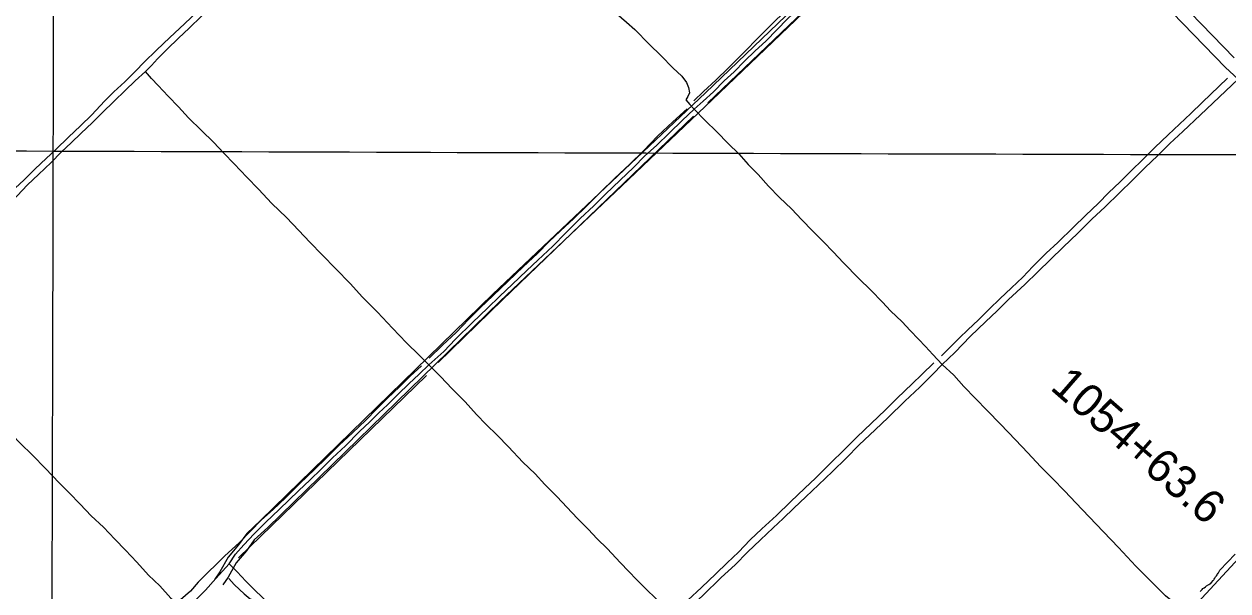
# Model space of a CAD drawing. Extents: x 3161514 to 3199414, y 831166 to 856601.
# Drawn here: x 3191795 to 3195450, y 841285 to 843007 of the extents above; entities that cross this region are included whole.
import ezdxf

# ---------------------------------------------------------------- set-up
doc = ezdxf.new("R2010")
doc.units = 0
for name, color, linetype in [('V-GRID-MAJR', 7, 'Continuous'), ('V-ROAD-CNTR', 7, 'Continuous'), ('V-SITE-VEGE', 7, 'Continuous'), ('V-SURV-IDEN', 7, 'Continuous'), ('V-TOPO-SHOR', 7, 'Continuous')]:
    doc.layers.add(name, color=color, linetype=linetype)

msp = doc.modelspace()

# ---------------------------------------------------------------- linework, layer by layer
at = {"layer": 'V-GRID-MAJR'}
for points in [[(3191868.813, 836560.569), (3191883.798, 842621.023), (3191898.788, 848683.42), (3191913.778, 854745.858), (3191913.7830000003, 854747.76)], [(3165722.25, 842695.223), (3170954.554, 842678.861), (3176186.862, 842663.26), (3181419.1720000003, 842648.42), (3186651.484, 842634.341), (3191883.798, 842621.023), (3197116.113, 842608.466), (3197116.114, 842608.466)]]:
    msp.add_spline(points, degree=3, dxfattribs=at)
at = {"layer": 'V-ROAD-CNTR'}
for points in [[(3195091.441780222, 843982.0380084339), (3194693.490576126, 843594.0597843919), (3193863.4942361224, 842798.0953763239), (3193579.1478048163, 842528.3749157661)], [(3195117.135728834, 843965.1910421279), (3194714.344534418, 843572.493827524), (3193884.20019471, 842776.3854197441), (3193609.337744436, 842515.6619411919)], [(3193579.1478048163, 842528.3749157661), (3193218.165526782, 842185.9616005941), (3192514.1949347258, 841500.0619723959), (3192470.860021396, 841459.9950525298), (3192446.21307069, 841425.42012168), (3192414.4181342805, 841387.4101977), (3192389.409184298, 841343.0502864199), (3192373.6412158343, 841321.1523302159)], [(3193609.337744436, 842515.6619411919), (3193238.957485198, 842164.3336438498), (3192534.8488934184, 841478.3020159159), (3192493.495976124, 841440.0650923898), (3192469.9690231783, 841407.062158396), (3192439.1980847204, 841370.276231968), (3192414.7251336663, 841326.87031878), (3192397.987167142, 841303.6223652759)]]:
    msp.add_lwpolyline(points, dxfattribs=at)
at = {"layer": 'V-SITE-VEGE'}
for p, q in [((3195365.9050000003, 842730.7270000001), (3195480.833, 842839.7050000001)), ((3195425.404, 841348.042), (3195471.4220000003, 841396.659)), ((3195419.633, 841338.8420000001), (3195420.943, 841340.473)), ((3195420.943, 841340.473), (3195422.254, 841342.756)), ((3195422.254, 841342.756), (3195424.5500000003, 841346.344)), ((3195424.5500000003, 841346.344), (3195425.404, 841348.042)), ((3195384.921, 841300.707), (3195392.1180000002, 841304.936)), ((3195392.1180000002, 841304.936), (3195395.063, 841307.2170000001)), ((3195395.063, 841307.2170000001), (3195397.35, 841308.1900000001)), ((3195397.35, 841308.1900000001), (3195400.2970000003, 841311.121)), ((3195400.2970000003, 841311.121), (3195404.557, 841316.667)), ((3195404.557, 841316.667), (3195406.849, 841318.946)), ((3195406.849, 841318.946), (3195407.832, 841321.234)), ((3195407.832, 841321.234), (3195409.8000000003, 841324.492)), ((3195409.8000000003, 841324.492), (3195412.4220000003, 841327.7519999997)), ((3195412.4220000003, 841327.7519999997), (3195415.043, 841331.666)), ((3195415.043, 841331.666), (3195417.3370000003, 841334.601)), ((3195417.3370000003, 841334.601), (3195418.322, 841336.561)), ((3195418.322, 841336.561), (3195419.633, 841338.8420000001)), ((3195364.957, 841283.4400000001), (3195366.921, 841285.3960000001)), ((3195366.921, 841285.3960000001), (3195371.179, 841289.9589999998)), ((3195371.179, 841289.9589999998), (3195373.796, 841292.238)), ((3195373.796, 841292.238), (3195377.069, 841294.518)), ((3195377.069, 841294.518), (3195381.323, 841297.774)), ((3195381.323, 841297.774), (3195384.921, 841300.707))]:
    msp.add_line(p, q, dxfattribs=at)
for points in [[(3195480.833, 842839.7050000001), (3195442.685, 842874.5), (3195248.278, 843075.393), (3194937.003, 843402.0750000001), (3194730.659, 843612.049)], [(3194435.786, 843338.653), (3194393.843, 843296.902), (3194364.2290000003, 843268.837), (3194327.166, 843232.8250000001), (3194295.424, 843202.109), (3194266.254, 843175.544), (3194239.208, 843148.005), (3194214.821, 843122.403), (3194182.718, 843090.095), (3194146.008, 843053.465), (3194111.608, 843021.34), (3194081.721, 842990.2660000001)], [(3193509.893, 843119.605), (3193558.7970000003, 843071.721), (3193593.048, 843038.465), (3193623.512, 843012.208), (3193649.1180000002, 842990.208), (3193692.4560000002, 842945.343), (3193728.646, 842909.605), (3193764.132, 842873.4400000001)], [(3192370.838, 843066.801), (3192333.362, 843030.112), (3192296.328, 842994.1240000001), (3192263.882, 842963.756), (3192228.965, 842930.669), (3192199.6890000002, 842900.997), (3192181.429, 842880.804), (3192163.2120000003, 842862.5480000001)], [(3194081.721, 842990.2660000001), (3194046.34, 842954.5160000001), (3194014.776, 842925.3030000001), (3193982.059, 842893.4400000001), (3193950.756, 842861.307), (3193919.9930000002, 842833.952), (3193888.0670000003, 842800.318), (3193856.947, 842772.2540000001), (3193829.291, 842748.1630000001)], [(3192163.2120000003, 842862.5480000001), (3192132.447, 842833.952), (3192101.944, 842804.385), (3192068.429, 842772.082), (3192032.253, 842737.041), (3192002.282, 842708.1780000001)], [(3192369.569, 842648.4180000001), (3192333.286, 842683.18), (3192294.534, 842721.488), (3192263.294, 842754.914), (3192232.136, 842787.188), (3192202.485, 842819.8150000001), (3192181.921, 842841.36), (3192163.2120000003, 842862.5480000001)], [(3193764.132, 842873.4400000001), (3193791.679, 842848.605), (3193805.526, 842829.5530000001), (3193812.5670000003, 842814.408), (3193815.36, 842797.68), (3193810.0270000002, 842786.279), (3193804.342, 842776.561), (3193815.633, 842761.848), (3193829.291, 842748.1630000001)], [(3193829.291, 842748.1630000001), (3193792.828, 842714.238), (3193754.08, 842676.549), (3193714.623, 842637.889), (3193679.25, 842606.03), (3193644.668, 842571.341), (3193605.0330000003, 842532.769), (3193560.432, 842489.8740000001), (3193524.696, 842454.39), (3193482.7630000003, 842416.088), (3193439.665, 842372.394), (3193399.7600000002, 842331.789)], [(3193829.291, 842748.1630000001), (3193862.7660000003, 842713.3470000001), (3193898.429, 842679.027), (3193932.588, 842644.1780000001), (3193964.631, 842612.698), (3193993.487, 842580.252), (3194023.144, 842549.837), (3194055.267, 842514.2880000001), (3194088.279, 842480.416), (3194124.649, 842445.387)], [(3194993.946, 842371.409), (3195036.954, 842414.485), (3195076.7630000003, 842451.818), (3195120.387, 842494.007), (3195160.11, 842532.579), (3195198.418, 842571.0650000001), (3195235.745, 842606.014), (3195273.078, 842643.617), (3195312.707, 842679.9770000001), (3195365.9050000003, 842730.7270000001)], [(3192002.282, 842708.1780000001), (3191967.79, 842674.55), (3191939.063, 842646.746), (3191908.031, 842617.976), (3191876.906, 842586.552), (3191838.954, 842549.3030000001), (3191805.265, 842518.06), (3191774.401, 842485.221), (3191736.454, 842449.389), (3191701.9620000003, 842416.289), (3191676.251, 842392.551)], [(3192822.883, 842177.773), (3192784.758, 842218.647), (3192741.772, 842262.98), (3192699.936, 842305.984), (3192662.779, 842344.732), (3192628.975, 842380.197), (3192591.64, 842419.033), (3192547.413, 842461.601), (3192507.08, 842504.867), (3192471.156, 842541.577), (3192433.1180000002, 842582.626), (3192401.784, 842614.724), (3192369.569, 842648.4180000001)], [(3194124.649, 842445.387), (3194155.716, 842412.14), (3194188.903, 842378.268), (3194221.915, 842345.103), (3194251.132, 842315.31), (3194283.0810000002, 842281.3520000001)], [(3194581.771, 841973.202), (3194620.3000000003, 842009.796), (3194668.275, 842059.052), (3194713.761, 842102.388), (3194749.3140000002, 842135.572), (3194783.276, 842169.9990000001), (3194832.747, 842215.626), (3194872.739, 842254.46), (3194910.776, 842291.4450000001), (3194949.436, 842329.044), (3194993.946, 842371.409)], [(3193399.7600000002, 842331.789), (3193354.544, 842289.692), (3193321.119, 842258.095), (3193276.431, 842215.552), (3193239.281, 842179.897), (3193201.862, 842143.973), (3193156.8200000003, 842100.813), (3193105.2120000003, 842049.441), (3193069.387, 842012.63), (3193024.136, 841971.721)], [(3194283.0810000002, 842281.3520000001), (3194329.066, 842234.003), (3194365.171, 842198.974), (3194400.74, 842161.911), (3194425.275, 842135.934), (3194460.323, 842102.589), (3194485.3880000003, 842076.432), (3194510.276, 842049.568), (3194531.634, 842027.136), (3194553.433, 842003.0210000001), (3194581.771, 841973.202)], [(3193024.136, 841971.721), (3192994.471, 842001.587), (3192955.717, 842038.834), (3192913.794, 842083.52), (3192868.253, 842131.576), (3192822.883, 842177.773)], [(3192770.6350000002, 841726.349), (3192813.465, 841769.6020000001), (3192844.85, 841798.373), (3192871.544, 841826.002), (3192898.5840000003, 841850.889), (3192930.418, 841882.932), (3192963.046, 841913.822), (3192994.698, 841943.7440000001), (3193024.136, 841971.721)], [(3193024.136, 841971.721), (3193058.823, 841936.252), (3193094.8370000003, 841899.456), (3193133.583, 841859.022), (3193168.975, 841821.255), (3193197.745, 841790.578), (3193231.379, 841758.385), (3193265.536, 841722.652)], [(3194804.727, 841744.348), (3194759.626, 841791.694), (3194718.758, 841832.838), (3194683.0100000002, 841869.725), (3194648.237, 841906.167), (3194617.349, 841940.211), (3194581.771, 841973.202), (3194553.832, 841943.011)], [(3194553.832, 841943.011), (3194514.374, 841903.73), (3194468.625, 841861.721), (3194418.349, 841811.496), (3194378.362, 841774.429), (3194329.865, 841729.066), (3194290.2260000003, 841688.7270000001), (3194248.994, 841647.769)], [(3191738.867, 841780.365), (3191782.112, 841734.702), (3191821.8370000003, 841696.302), (3191858.554, 841657.911), (3191902.154, 841612.515), (3191932.255, 841582.718), (3191965.7090000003, 841549.111), (3191998.539, 841513.381), (3192035.97, 841478.438), (3192070.041, 841442.885), (3192102.52, 841409.013)], [(3195072.245, 841464.786), (3195028.467, 841510.094), (3194987.955, 841552.654), (3194954.065, 841588.473), (3194917.524, 841626.601), (3194881.068, 841662.7810000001), (3194841.882, 841704.273), (3194804.727, 841744.348)], [(3192417.31, 841367.471), (3192436.696, 841396.672), (3192462.3310000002, 841425.188), (3192493.9930000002, 841458.824), (3192529.196, 841494.398), (3192569.095, 841532.35), (3192599.862, 841561.652), (3192628.59, 841589.542), (3192663.702, 841622.9940000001), (3192696.421, 841654.9450000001), (3192731.444, 841689.192), (3192770.6350000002, 841726.349)], [(3193265.536, 841722.652), (3193309.312, 841676.2810000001), (3193346.125, 841640.986), (3193375.866, 841608.449), (3193412.937, 841571.028), (3193442.237, 841539.2000000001), (3193474.719, 841505.419), (3193507.288, 841472.964), (3193535.18, 841443.262), (3193565.545, 841413.8200000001)], [(3194248.994, 841647.769), (3194206.346, 841607.878), (3194168.219, 841570.805), (3194131.955, 841536.296), (3194099.416, 841505.4940000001), (3194068.915, 841476.724), (3194030.968, 841440.714), (3193991.599, 841402.582), (3193953.469, 841364.539)], [(3195305.915, 841239.711), (3195286.472, 841248.78), (3195260.511, 841270.2490000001), (3195221.759, 841308.735), (3195170.299, 841360.785), (3195116.991, 841417.438), (3195072.245, 841464.786)], [(3193565.545, 841413.8200000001), (3193605.703, 841370.908), (3193629.707, 841345.019), (3193654.863, 841318.9500000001), (3193679.668, 841294.919), (3193716.565, 841257.942), (3193750.457, 841223.005), (3193771.9020000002, 841199.247), (3193807.117, 841162.098), (3193845.949, 841120.87)], [(3192102.52, 841409.013), (3192137.383, 841372.483), (3192173.125, 841333.387), (3192206.757, 841300.84), (3192240.836, 841263.1240000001)], [(3192240.836, 841263.1240000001), (3192260.2630000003, 841246.801), (3192279.674, 841223.755), (3192310.703, 841252.171), (3192345.464, 841287.214), (3192377.218, 841322.708), (3192417.31, 841367.471), (3192441.494, 841343.086), (3192468.504, 841315.421), (3192497.72, 841285.7170000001), (3192534.973, 841249.801), (3192566.316, 841221.064)], [(3193953.469, 841364.539), (3193911.713, 841326.415), (3193856.028, 841271.6), (3193820.65, 841238.595), (3193776.403, 841194.9010000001), (3193742.091, 841162.866), (3193700.326, 841121.201)]]:
    msp.add_lwpolyline(points, dxfattribs=at)
at = {"layer": 'V-TOPO-SHOR'}
for p, q in [((3193871.144517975, 842767.2020910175), (3194729.8649335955, 843590.5113554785)), ((3195371.374, 842768.086), (3195448.098, 842842.779)), ((3193016.8504962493, 841939.4664326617), (3192445.845683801, 841386.1671957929))]:
    msp.add_line(p, q, dxfattribs=at)
for points in [[(3195469.0727140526, 842904.4203017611), (3194769.70247865, 843625.9225066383), (3195207.9154742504, 844059.7091083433), (3195584.158955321, 844413.8206199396)], [(3193844.5861546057, 839659.8735767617), (3194672.3218129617, 840514.1675984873), (3194902.494295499, 840748.7664749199), (3195066.270869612, 840885.9846856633), (3195345.133684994, 841235.6698033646), (3195659.407651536, 841576.5021332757), (3196354.351493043, 842337.8418832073), (3196827.975639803, 842882.2883322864), (3196947.4882749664, 843023.9329369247), (3197022.736971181, 843094.755239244), (3197124.5440307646, 843196.5622988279)], [(3194219.4020000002, 843155.605), (3194173.271, 843110.559), (3194123.881, 843062.621), (3194072.1180000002, 843013.814), (3194023.6950000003, 842964.995), (3193982.049, 842922.487)], [(3192001.009, 842731.083), (3192038.651, 842772.334), (3192067.22, 842800.858), (3192101.0470000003, 842831.525), (3192133.502, 842863.486), (3192159.399, 842891.243), (3192197.199, 842926.894), (3192237.3310000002, 842965.468), (3192266.845, 842992.959), (3192300.418, 843024.9180000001), (3192335.287, 843058.853), (3192366.88, 843090.902)], [(3193982.049, 842922.487), (3193933.8880000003, 842874.109), (3193895.417, 842836.426), (3193858.092, 842801.551), (3193827.896, 842773.333)], [(3195371.374, 842768.086), (3195337.508, 842734.638), (3195302.682, 842702.329), (3195268.734, 842670.544), (3195227.764, 842631.333)], [(3191634.836, 842375.843), (3191669.335, 842412.523), (3191703.944, 842445.598), (3191733.722, 842475.4130000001), (3191768.2430000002, 842508.058), (3191794.824, 842533.402), (3191828.401, 842566.909), (3191862.316, 842598.0920000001), (3191890.972, 842626.1), (3191929.896, 842663.558), (3191966.315, 842698.008), (3192001.009, 842731.083)], [(3193807.9790000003, 842749.677), (3193764.406, 842709.544), (3193719.072, 842667.22), (3193675.134, 842621.8200000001), (3193632.611, 842580.3690000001), (3193588.86, 842538.743), (3193544.136, 842494.75)], [(3193826.8805790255, 842727.3645459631), (3193247.022978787, 842169.6389151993), (3193052.261647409, 841979.3039777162)], [(3195227.764, 842631.333), (3195190.3880000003, 842594.1290000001), (3195156.788, 842561.818), (3195122.046, 842527.145), (3195087.13, 842493.611), (3195056.772, 842463.219), (3195017.381, 842424.88), (3194980.8850000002, 842389.511)], [(3193544.136, 842494.75), (3193502.139, 842453.208), (3193463.844, 842415.875), (3193423.1750000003, 842378.458), (3193387.961, 842345.072), (3193353.184, 842310.1900000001), (3193310.1350000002, 842269.179), (3193263.216, 842225.1020000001)], [(3194980.8850000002, 842389.511), (3194933.773, 842343.6630000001), (3194898.247, 842311.268), (3194856.924, 842270.746), (3194827.001, 842238.25), (3194792.3510000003, 842205.767), (3194756.998, 842172.671), (3194725.852, 842141.755)], [(3193263.216, 842225.1020000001), (3193219.198, 842182.162), (3193179.231, 842144.481), (3193145.068, 842110.123), (3193106.326, 842069.806), (3193065.7430000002, 842031.337), (3193024.4560000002, 841991.9)], [(3194725.852, 842141.755), (3194692.4250000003, 842108.831), (3194660.056, 842078.5310000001), (3194635.052, 842053.551), (3194579.781, 841999.5800000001)], [(3193001.717, 841968.8150000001), (3192966.772, 841937.272), (3192934.548, 841905.02), (3192898.543, 841870.757), (3192865.349, 841837.1020000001), (3192832.245, 841804.236)], [(3194556.446, 841978.187), (3194520.2120000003, 841942.644), (3194490.736, 841914.349), (3194445.467, 841870.247), (3194408.881, 841833.742), (3194367.387, 841794.533), (3194323.17, 841752.0040000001)], [(3192832.245, 841804.236), (3192791.75, 841765.416), (3192751.431, 841727.561), (3192712.428, 841688.297), (3192676.509, 841653.681), (3192631.7, 841611.093)], [(3194323.17, 841752.0040000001), (3194285.882, 841714.7980000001), (3194242.457, 841672.355), (3194198.06, 841627.289), (3194165.691, 841597.513), (3194121.653, 841555.947)], [(3192631.7, 841611.093), (3192588.2970000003, 841568.501), (3192550.794, 841532.747), (3192515.145, 841500.1510000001), (3192482.217, 841466.935), (3192447.526, 841431.703)], [(3194121.653, 841555.947), (3194079.1040000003, 841514.112), (3194034.718, 841473.949), (3193999.715, 841440.677), (3193964.002, 841403.381), (3193929.002, 841370.7220000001), (3193894.784, 841336.7490000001)], [(3192447.526, 841431.703), (3192404.919, 841392.359), (3192381.236, 841368.256), (3192351.126, 841338.898), (3192323.571, 841311.819), (3192299.789, 841284.378), (3192269.954, 841258.532)], [(3192416.81, 841323.441), (3192432.784, 841304.8910000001), (3192448.509, 841289.699), (3192463.6350000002, 841276.831), (3192480.91, 841261.809), (3192494.421, 841256.8690000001), (3192514.549, 841246.834), (3192525.725, 841238.54), (3192537.157, 841229.041), (3192551.3370000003, 841216.091)], [(3193894.784, 841336.7490000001), (3193851.272, 841295.6190000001), (3193809.6920000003, 841257.025), (3193774.419, 841220.339)]]:
    msp.add_lwpolyline(points, dxfattribs=at)

# ---------------------------------------------------------------- texts
at = {"layer": 'V-SURV-IDEN'}
msp.add_text('1054+63.6', height=100, rotation=318.93555554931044, dxfattribs=at).set_placement((3194906.64314825, 841899.4940710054))

doc.saveas('drawing.dxf')
